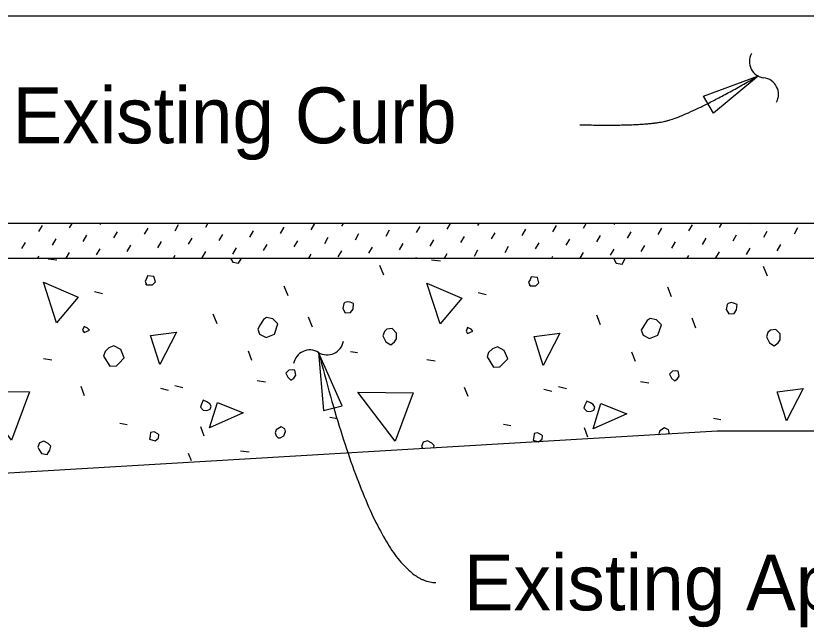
# Model space of a CAD drawing. Extents: x 21587 to 21656.3, y 56117.4 to 56157.3.
# Drawn here: x 21616.296 to 21619.149, y 56132.593 to 56134.801 of the extents above; entities that cross this region are included whole.
import ezdxf

# ---------------------------------------------------------------- set-up
doc = ezdxf.new("R2010")
doc.units = 0
for name, color, linetype in [('AdhocPoint_dp', 7, 'Continuous'), ('PlotBorder_dp', 7, 'Continuous'), ('SheetBorder_dp', 7, 'Continuous'), ('TextMisc', 7, 'Continuous')]:
    doc.layers.add(name, color=color, linetype=linetype)

msp = doc.modelspace()

# ---------------------------------------------------------------- linework, layer by layer
at = {"layer": 'AdhocPoint_dp'}
for p, q in [((21613.608, 56134.8009), (21621.5551, 56134.8009)), ((21624.3563, 56134.0511), (21613.608, 56134.0511)), ((21613.608, 56133.926), (21624.3563, 56133.926)), ((21618.8279, 56133.301), (21614.6079, 56133.0509)), ((21624.3563, 56133.301), (21618.8279, 56133.301))]:
    msp.add_line(p, q, dxfattribs=at)
at = {"layer": 'PlotBorder_dp'}
for points in [[(21618.9767, 56134.5845), (21618.814, 56134.4497), (21618.7787, 56134.5108)], [(21617.3888, 56133.5857), (21617.4059, 56133.3752), (21617.4742, 56133.3926)]]:
    msp.add_lwpolyline(points, close=True, dxfattribs=at)
for centre, start, end in [((21619.0033, 56134.636), 151.5267, 263.2539), ((21618.9893, 56134.5176), 331.5267, 83.2539), ((21617.4197, 56133.6363), 238.4384, 350.1656), ((21617.3573, 56133.5347), 58.4384, 170.1656)]:
    msp.add_arc(centre, 0.0596, start, end, dxfattribs=at)
for points in [[(21618.3321, 56134.4076), (21618.5489, 56134.4019), (21618.72, 56134.4362), (21618.9767, 56134.5845)], [(21617.3892, 56133.5857), (21617.6004, 56132.7545), (21617.8116, 56132.7545)]]:
    msp.add_open_spline(points, degree=2, dxfattribs=at)
at = {"layer": 'TextMisc'}
for p, q in [((21616.3793, 56134.0219), (21616.3922, 56134.0443)), ((21616.4899, 56134.0349), (21616.4993, 56134.0511)), ((21616.6005, 56134.0479), (21616.6024, 56134.0511)), ((21616.76, 56134.012), (21616.773, 56134.0344)), ((21616.8706, 56134.0249), (21616.8836, 56134.0473)), ((21616.9813, 56134.0379), (21616.9889, 56134.0511)), ((21617.0919, 56134.0509), (21617.092, 56134.0511)), ((21617.2514, 56134.015), (21617.2643, 56134.0374)), ((21617.362, 56134.028), (21617.375, 56134.0504)), ((21617.4726, 56134.0409), (21617.4785, 56134.0511)), ((21617.7427, 56134.018), (21617.7557, 56134.0404)), ((21617.8534, 56134.031), (21617.865, 56134.0511)), ((21617.964, 56134.044), (21617.9681, 56134.0511)), ((21618.1235, 56134.0081), (21618.1364, 56134.0305)), ((21618.2341, 56134.021), (21618.2471, 56134.0434)), ((21618.3447, 56134.034), (21618.3546, 56134.0511)), ((21618.4554, 56134.047), (21618.4578, 56134.0511)), ((21618.6148, 56134.0111), (21618.6278, 56134.0335)), ((21618.7255, 56134.0241), (21618.7384, 56134.0465)), ((21618.8361, 56134.037), (21618.8442, 56134.0511)), ((21618.9467, 56134.05), (21618.9474, 56134.0511)), ((21619.1062, 56134.0141), (21619.1192, 56134.0365)), ((21616.5387, 56133.9861), (21616.5517, 56134.0084)), ((21616.6494, 56133.999), (21616.6623, 56134.0214)), ((21617.0301, 56133.9891), (21617.0431, 56134.0115)), ((21617.1407, 56134.002), (21617.1537, 56134.0244)), ((21617.4108, 56133.9791), (21617.4238, 56134.0015)), ((21617.5215, 56133.9921), (21617.5344, 56134.0145)), ((21617.6321, 56134.0051), (21617.6451, 56134.0275)), ((21617.9022, 56133.9822), (21617.9152, 56134.0045)), ((21618.0128, 56133.9951), (21618.0258, 56134.0175)), ((21618.3936, 56133.9852), (21618.4065, 56134.0076)), ((21618.5042, 56133.9981), (21618.5172, 56134.0205)), ((21618.8849, 56133.9882), (21618.8979, 56134.0106)), ((21618.9956, 56134.0012), (21619.0085, 56134.0235)), ((21616.3175, 56133.9601), (21616.3304, 56133.9825)), ((21616.4281, 56133.9731), (21616.4411, 56133.9955)), ((21616.6982, 56133.9502), (21616.7112, 56133.9726)), ((21616.8088, 56133.9631), (21616.8218, 56133.9855)), ((21616.9195, 56133.9761), (21616.9324, 56133.9985)), ((21617.1896, 56133.9532), (21617.2025, 56133.9756)), ((21617.3002, 56133.9662), (21617.3132, 56133.9886)), ((21617.6809, 56133.9562), (21617.6939, 56133.9786)), ((21617.7916, 56133.9692), (21617.8045, 56133.9916)), ((21618.1723, 56133.9592), (21618.1853, 56133.9816)), ((21618.2829, 56133.9722), (21618.2959, 56133.9946)), ((21618.6637, 56133.9623), (21618.6766, 56133.9847)), ((21618.7743, 56133.9752), (21618.7873, 56133.9976)), ((21619.0444, 56133.9523), (21619.0574, 56133.9747)), ((21616.478, 56133.926), (21616.4899, 56133.9466)), ((21616.5876, 56133.9372), (21616.6005, 56133.9596)), ((21616.9683, 56133.9273), (21616.9813, 56133.9497)), ((21617.0789, 56133.9402), (21617.0919, 56133.9626)), ((21617.4597, 56133.9303), (21617.4726, 56133.9527)), ((21617.5703, 56133.9433), (21617.5833, 56133.9657)), ((21617.951, 56133.9333), (21617.964, 56133.9557)), ((21618.0617, 56133.9463), (21618.0746, 56133.9687)), ((21618.3333, 56133.926), (21618.3447, 56133.9458)), ((21618.4424, 56133.9363), (21618.4554, 56133.9587)), ((21618.553, 56133.9493), (21618.566, 56133.9717)), ((21618.8231, 56133.9264), (21618.8361, 56133.9488)), ((21618.9338, 56133.9394), (21618.9467, 56133.9617)), ((21616.3748, 56133.926), (21616.3793, 56133.9337)), ((21616.4123, 56133.9236), (21616.4441, 56133.9201)), ((21616.8645, 56133.926), (21616.8706, 56133.9367)), ((21617.2509, 56133.926), (21617.2514, 56133.9268)), ((21617.3541, 56133.926), (21617.362, 56133.9397)), ((21617.7406, 56133.926), (21617.7427, 56133.9298)), ((21617.7969, 56133.9201), (21617.8288, 56133.9165)), ((21617.8437, 56133.926), (21617.8534, 56133.9427)), ((21618.2302, 56133.926), (21618.2341, 56133.9328)), ((21618.7198, 56133.926), (21618.7255, 56133.9358)), ((21617.6243, 56133.8641), (21617.6102, 56133.8995)), ((21619.009, 56133.8606), (21618.9949, 56133.8959)), ((21616.5802, 56133.8051), (21616.6085, 56133.7981)), ((21617.2785, 56133.7892), (21617.2643, 56133.8246)), ((21617.9649, 56133.8016), (21617.9932, 56133.7945)), ((21618.6631, 56133.7857), (21618.649, 56133.8211)), ((21617.0221, 56133.6885), (21617.008, 56133.7238)), ((21618.4068, 56133.6849), (21618.3927, 56133.7203)), ((21617.3662, 56133.6767), (21617.3521, 56133.7121)), ((21618.7509, 56133.6732), (21618.7368, 56133.7085)), ((21617.1477, 56133.5559), (21617.1353, 56133.5895)), ((21617.5041, 56133.5883), (21617.5289, 56133.5848)), ((21618.5323, 56133.5524), (21618.52, 56133.5859)), ((21616.3952, 56133.5636), (21616.4253, 56133.5583)), ((21617.7799, 56133.5601), (21617.8099, 56133.5547)), ((21616.5437, 56133.4292), (21616.5313, 56133.4628)), ((21616.8701, 56133.4657), (21616.8984, 56133.4587)), ((21617.1665, 56133.484), (21617.1965, 56133.4787)), ((21617.9284, 56133.4257), (21617.916, 56133.4593)), ((21618.2548, 56133.4622), (21618.2831, 56133.4551)), ((21618.5512, 56133.4805), (21618.5812, 56133.4752)), ((21616.8177, 56133.4558), (21616.846, 56133.4487)), ((21618.2024, 56133.4522), (21618.2307, 56133.4451)), ((21617.4299, 56133.3515), (21617.4564, 56133.3462)), ((21618.8145, 56133.3479), (21618.8411, 56133.3426)), ((21616.671, 56133.3302), (21616.6975, 56133.3249)), ((21616.9762, 56133.2831), (21616.9638, 56133.3167)), ((21618.0557, 56133.3267), (21618.0822, 56133.3214)), ((21618.3609, 56133.2796), (21618.3485, 56133.3132)), ((21616.9302, 56133.1935), (21616.9196, 56133.2201)), ((21617.1064, 56133.2295), (21617.1382, 56133.2259))]:
    msp.add_line(p, q, dxfattribs=at)
for points in [[(21617.0705, 56133.926), (21617.0787, 56133.9112), (21617.0999, 56133.9077), (21617.1088, 56133.9236), (21617.1094, 56133.926)], [(21618.4533, 56133.926), (21618.4545, 56133.9236)], [(21618.4545, 56133.9236), (21618.4634, 56133.9077), (21618.4846, 56133.9041), (21618.4934, 56133.9201), (21618.4949, 56133.926)], [(21616.7676, 56133.8299), (21616.7888, 56133.8299), (21616.7994, 56133.8405), (21616.7941, 56133.8599), (21616.7711, 56133.8617), (21616.7676, 56133.8511), (21616.7623, 56133.8423), (21616.7676, 56133.8299), (21616.764, 56133.8334)], [(21616.4429, 56133.6926), (21616.3952, 56133.8394), (21616.5207, 56133.7846), (21616.4429, 56133.6926)], [(21617.8276, 56133.6891), (21617.7799, 56133.8358), (21617.9054, 56133.781), (21617.8276, 56133.6891)], [(21618.1523, 56133.8264), (21618.1735, 56133.8264), (21618.1841, 56133.837), (21618.1788, 56133.8564), (21618.1558, 56133.8582), (21618.1523, 56133.8476), (21618.147, 56133.8387), (21618.1523, 56133.8264), (21618.1487, 56133.8299)], [(21617.4758, 56133.7439), (21617.4847, 56133.728), (21617.5041, 56133.7298), (21617.513, 56133.7421), (21617.5147, 56133.7616), (21617.5023, 56133.7669), (21617.4935, 56133.7686), (21617.4829, 56133.7651), (21617.4794, 56133.7616), (21617.4758, 56133.7439)], [(21618.8605, 56133.7404), (21618.8693, 56133.7245), (21618.8888, 56133.7262), (21618.8976, 56133.7386), (21618.8994, 56133.758), (21618.887, 56133.7633), (21618.8782, 56133.7651), (21618.8676, 56133.7616), (21618.864, 56133.758), (21618.8605, 56133.7404)], [(21617.1759, 56133.6514), (21617.1989, 56133.639), (21617.229, 56133.6514), (21617.2413, 56133.6885), (21617.2237, 56133.7062), (21617.2007, 56133.7115), (21617.1901, 56133.7044), (21617.1777, 56133.6849), (21617.1689, 56133.669), (21617.1759, 56133.6514)], [(21618.5606, 56133.6478), (21618.5836, 56133.6354), (21618.6136, 56133.6478), (21618.626, 56133.6849), (21618.6083, 56133.7026), (21618.5854, 56133.7079), (21618.5748, 56133.7008), (21618.5624, 56133.6814), (21618.5535, 56133.6655), (21618.5606, 56133.6478)], [(21616.5419, 56133.6573), (21616.5614, 56133.6661), (21616.5543, 56133.6732), (21616.5419, 56133.6785), (21616.5366, 56133.6661), (21616.5419, 56133.6573)], [(21617.6208, 56133.6449), (21617.6314, 56133.6237), (21617.6491, 56133.6131), (21617.6632, 56133.6237), (21617.6703, 56133.6343), (21617.6703, 56133.6555), (21617.6544, 56133.6714), (21617.6349, 56133.6697), (21617.6261, 56133.6608), (21617.6208, 56133.6449)], [(21617.9266, 56133.6537), (21617.9461, 56133.6626), (21617.939, 56133.6697), (21617.9266, 56133.675), (21617.9213, 56133.6626), (21617.9266, 56133.6537)], [(21619.0055, 56133.6414), (21619.0161, 56133.6202), (21619.0338, 56133.6096), (21619.0479, 56133.6202), (21619.055, 56133.6308), (21619.055, 56133.652), (21619.0391, 56133.6679), (21619.0196, 56133.6661), (21619.0108, 56133.6573), (21619.0055, 56133.6414)], [(21616.8153, 56133.5417), (21616.7817, 56133.646), (21616.8754, 56133.6584), (21616.8153, 56133.5417)], [(21618.2, 56133.5382), (21618.1664, 56133.6425), (21618.2601, 56133.6549), (21618.2, 56133.5382)], [(21616.6126, 56133.5724), (21616.6356, 56133.5353), (21616.6586, 56133.5371), (21616.6674, 56133.5459), (21616.6869, 56133.5654), (21616.6745, 56133.5954), (21616.6498, 56133.6096), (21616.6321, 56133.6025), (21616.6179, 56133.5883), (21616.6126, 56133.5724)], [(21617.9973, 56133.5689), (21618.0203, 56133.5318), (21618.0433, 56133.5335), (21618.0521, 56133.5424), (21618.0716, 56133.5618), (21618.0592, 56133.5919), (21618.0344, 56133.606), (21618.0168, 56133.5989), (21618.0026, 56133.5848), (21617.9973, 56133.5689)], [(21617.2778, 56133.4964), (21617.2884, 56133.4858), (21617.2991, 56133.4929), (21617.3061, 56133.5035), (21617.3026, 56133.5212), (21617.2938, 56133.5229), (21617.2814, 56133.5212), (21617.2708, 56133.5106), (21617.2778, 56133.4964)], [(21618.6625, 56133.4929), (21618.6731, 56133.4823), (21618.6837, 56133.4893), (21618.6908, 56133.4999), (21618.6873, 56133.5176), (21618.6784, 56133.5194), (21618.6661, 56133.5176), (21618.6554, 56133.507), (21618.6625, 56133.4929)], [(21616.2803, 56133.2684), (21616.146, 56133.4451), (21616.3457, 56133.4434), (21616.2803, 56133.2684)], [(21617.665, 56133.2648), (21617.5306, 56133.4416), (21617.7304, 56133.4398), (21617.665, 56133.2648)], [(21619.0778, 56133.3385), (21619.0443, 56133.4428), (21619.1379, 56133.4551), (21619.0778, 56133.3385)], [(21616.9726, 56133.3773), (21616.985, 56133.3756), (21616.9974, 56133.3809), (21617.0009, 56133.3915), (21616.9956, 56133.4003), (21616.985, 56133.4074), (21616.9726, 56133.4127), (21616.9656, 56133.3986), (21616.962, 56133.388), (21616.9726, 56133.3773)], [(21616.995, 56133.3126), (21617.0233, 56133.4045), (21617.117, 56133.3674), (21616.995, 56133.3126)], [(21618.3573, 56133.3738), (21618.3697, 56133.372), (21618.3821, 56133.3773), (21618.3856, 56133.388), (21618.3803, 56133.3968), (21618.3697, 56133.4039), (21618.3573, 56133.4092), (21618.3503, 56133.395), (21618.3467, 56133.3844), (21618.3573, 56133.3738)], [(21618.3797, 56133.309), (21618.408, 56133.401), (21618.5017, 56133.3638), (21618.3797, 56133.309)], [(21616.7788, 56133.2719), (21616.7983, 56133.2666), (21616.8106, 56133.2754), (21616.8124, 56133.2878), (21616.8089, 56133.2914), (21616.7947, 56133.2984), (21616.7824, 56133.2967), (21616.7806, 56133.2843), (21616.7788, 56133.2719)], [(21617.2425, 56133.2772), (21617.2496, 56133.2772), (21617.2637, 56133.2843), (21617.269, 56133.3002), (21617.2672, 56133.309), (21617.2531, 56133.3161), (21617.2354, 56133.3055), (21617.2319, 56133.2949), (21617.2354, 56133.2843), (21617.2425, 56133.2772)], [(21618.1635, 56133.2684), (21618.1829, 56133.2631), (21618.1953, 56133.2719), (21618.1971, 56133.2843), (21618.1935, 56133.2878), (21618.1794, 56133.2949), (21618.167, 56133.2931), (21618.1653, 56133.2807), (21618.1635, 56133.2684)], [(21618.6514, 56133.2899), (21618.6537, 56133.2967), (21618.6519, 56133.3055), (21618.6378, 56133.3126), (21618.6201, 56133.302), (21618.6166, 56133.2914), (21618.6177, 56133.2878)], [(21616.3793, 56133.2366), (21616.3881, 56133.2206), (21616.4094, 56133.2171), (21616.4182, 56133.233), (21616.4217, 56133.2472), (21616.4129, 56133.256), (21616.397, 56133.2648), (21616.3811, 56133.2595), (21616.3758, 56133.2436), (21616.3793, 56133.2366)], [(21617.8048, 56133.2422), (21617.8064, 56133.2488), (21617.7976, 56133.2577), (21617.7817, 56133.2665), (21617.7657, 56133.2612), (21617.7604, 56133.2453), (21617.7633, 56133.2396)]]:
    msp.add_lwpolyline(points, dxfattribs=at)

# ---------------------------------------------------------------- texts
at = {"layer": 'SheetBorder_dp'}
for s, p in [('Existing Curb', (21616.2837, 56134.3406)), ('Existing Approach Slab', (21617.9127, 56132.654))]:
    msp.add_text(s, height=0.2016, dxfattribs=at).set_placement(p)

doc.saveas('drawing.dxf')
